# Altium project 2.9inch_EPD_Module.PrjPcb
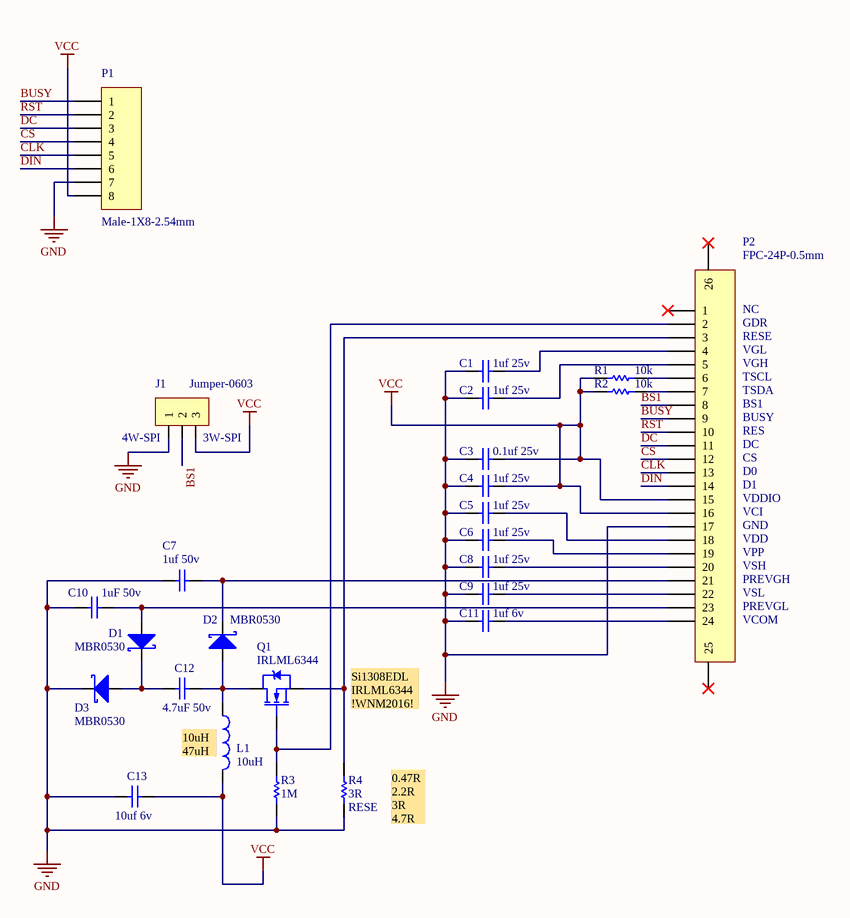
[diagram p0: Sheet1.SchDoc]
1 sheet, 25 parts. Net scope: global (net labels, ports and power ports of the same name join across sheets).
Board file: PCB1.PcbDoc

## Sheet Sheet1.SchDoc
size A4

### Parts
C1  1uf 25v  [0603-CAP]
C2  1uf 25v  [0603-CAP]
C3  0.1uf 25v  [0603-CAP]
C4  1uf 25v  [0603-CAP]
C5  1uf 25v  [0603-CAP]
C6  1uf 25v  [0603-CAP]
C7  1uf 50v  [0603-CAP]
C8  1uf 25v  [0603-CAP]
C9  1uf 25v  [0603-CAP]
C10  1uF 50v  [0603-CAP]
C11  1uf 6v  [0603-CAP]
C12  4.7uF 50v  [0805-CAP]
C13  10uf 6v  [0805-CAP]
D1  MBR0530  [SOD-123-DIODE-SC_M]
D2  MBR0530  [SOD-123-DIODE-SC_M]
D3  MBR0530  [SOD-123-DIODE-SC_M]
J1  Jumper-0603  [0603-JUMPER]
L1  10uH  [NR_4020_M]
P1  Male-1X8-2.54mm  [MALE_1X8_2.54MM]
P2  FPC-24P-0.5mm  [FPC0.5 2H-WS-24P_M]
Q1  IRLML6344  [SOT-23-3_M]
R1  10k  [0603-RES]
R2  10k  [0603-RES]
R3  1M  [0603-RES]
R4  3R  [0603-RES]

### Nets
GND: C1.1 C2.1 C3.1 C4.1 C5.1 C6.1 C7.1 C8.1 C9.1 C10.1 C11.1 C13.1 D3.1(K) J1.1 P1.7 P2.17 R3.1 R4.1
VCC: C3.2 C4.2 C13.2 J1.3 L1.2 P1.8 P2.15 P2.16 R1.1 R2.1
BS1: J1.2 P2.8
BUSY: P1.1 P2.9
CLK: P1.5 P2.13
CS: P1.4 P2.12
DC: P1.3 P2.11
DIN: P1.6 P2.14
RST: P1.2 P2.10
NetC1_2: C1.2 P2.4
NetC2_2: C2.2 P2.5
NetC5_2: C5.2 P2.18
NetC6_2: C6.2 P2.19
NetC7_2: C7.2 D2.1(K) P2.21
NetC8_2: C8.2 P2.20
NetC9_2: C9.2 P2.22
NetC10_2: C10.2 D1.2(A) P2.23
NetC11_2: C11.2 P2.24
NetC12_1: C12.1 D1.1(K) D3.2(A)
NetC12_2: C12.2 D2.2(A) L1.1 Q1.3(D)
NetP2_2: P2.2 Q1.1(G) R3.2
NetP2_3: P2.3 Q1.2(S) R4.2
NetP2_6: P2.6 R1.2
NetP2_7: P2.7 R2.2

Not connected (* = marked no-connect by the designer): P2 1* 25* 26*

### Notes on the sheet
- (near P2) VGL
- (near P2) RESE
- (near P2) GDR
- (near P2) NC
- (near P2) BS1
- (near P2) TSDA
- (near P2) TSCL
- (near P2) VGH
- (near J1) 4W-SPI
- (near J1) 3W-SPI
- (near P2) D1
- (near P2) D0
- (near P2) CS
- (near P2) DC
- (near P2) RES
- (near P2) BUSY
- (near P2) VDD
- (near P2) GND
- (near P2) VCI
- (near P2) VDDIO
- (near P2) VCOM
- (near P2) PREVGL
- (near P2) VSL
- (near P2) PREVGH
- (near P2) VSH
- (near P2) VPP
- (near L1) 10uH
  47uH
- Si1308EDL
  IRLML6344
  !WNM2016!
- (near R4) RESE
- (near R4) 0.47R
  2.2R
  3R
  4.7R

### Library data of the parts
C1-C11 = CAP-0603
C12 C13 = CAP-0805
D1-D3 = Diode-Schottky-SOD123
L1 = Inductor-NR4020
P1 = Male-1X8-2.54mm: System: Connector
Q1 = NMOS-SOT23-3
R1-R4 = RES-0603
